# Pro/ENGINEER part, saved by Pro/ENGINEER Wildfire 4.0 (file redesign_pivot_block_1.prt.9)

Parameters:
  METRIC = "NO"

Other parameters: PITCH, DRILL_POINT_ANGLE, DRILL_DEPTH, DRILL_DIAMETER, THREAD_DIAMETER, THREADS_PER_INCH, THREAD_DEPTH, THREAD_LENGTH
